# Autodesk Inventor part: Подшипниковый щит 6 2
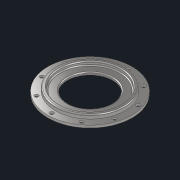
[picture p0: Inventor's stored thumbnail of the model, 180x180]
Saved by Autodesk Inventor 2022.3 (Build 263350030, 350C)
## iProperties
Created: 2022-08
Part Number: Подшипниковый щит 6 2
Material: Сталь 40ХНМА
Document SubType Name: Modeling
Designer: Карташов
Density: 7.85 g/cm^3
Appearance: С умеренной полировкой
Author: Карташов
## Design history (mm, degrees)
sketch "Эскиз1"
  geometry: L1 (0, 0)-(0, 34.001); L2 (47, -6)-(85, -6); L3 (85, -6)-(85, -1); L4 (85, -1)-(70, -1); L5 (70, -1)-(70, 5); L6 (68, 7)-(64, 7); L7 (62, 5)-(62, 2); L8 (45, -4)-(45, -2); L9 (47, 0)-(60, 0); A1 r 2 centre (60, 2) between (60, 0) and (62, 2); A2 r 2 centre (68, 5) between (70, 5) and (68, 7); A3 r 2 centre (64, 5) between (64, 7) and (62, 5); A4 r 2 centre (47, -2) between (47, 0) and (45, -2); A5 r 2 centre (47, -4) between (45, -4) and (47, -6); 6 further points
  constraints: 18 end point, 10 point on circle, 10 tangent, 8 point on line, 5 centre point, 4 horizontal, 4 vertical, 2 midpoint, 1 equal radius, 1 horizontal alignment, 1 perpendicular
  dimensions: "d0" = 140 diameter of L5 point (0, 17); "d1" = 170 diameter of L3 L1; "d4" = 5 distance of L2.end L3.end; "d6" = 8 distance of point (70, 7) point (62, 7); "d7" = 2 radius of A1; "d24" = 2 radius of A2; "d25" = 2 radius of A3 (derived); "d27" = 90 diameter of L8 L1; "d28" = 13 distance between parallel lines of L6 L2; "d29" = 7 distance between parallel lines of L6 L9; "d30" = 2 radius of A4
revolve "Вращение1" sketch "Эскиз1" stored, may be unused: angle "d9" = 90 deg
sketch "Эскиз2"
  geometry: C1 r 70 at (0, 0) reference; C2 r 85 at (0, 0) reference; 2 further points
  constraints: 1 vertical alignment
  dimensions: "d10" = 77.5 distance of point (0, 0) point (0, -77.5)
  node "Спроецированная петля1"
sketch "Эскиз3"
  geometry: 2 further points
hole "Отверстие1" sketch "Эскиз3" at (0, 77.5) diameter "d11" = 8; stored, may be unused: countersink angle "d15" = 90 deg, drill point angle "d17" = 0 deg; dims "d12" = 6, "d13" = 13, "d14" = 1, "d16" = 22.5
pattern_circular "Круговой массив1" dims angle "d19" = 360 deg
node "Твердое тело1"
